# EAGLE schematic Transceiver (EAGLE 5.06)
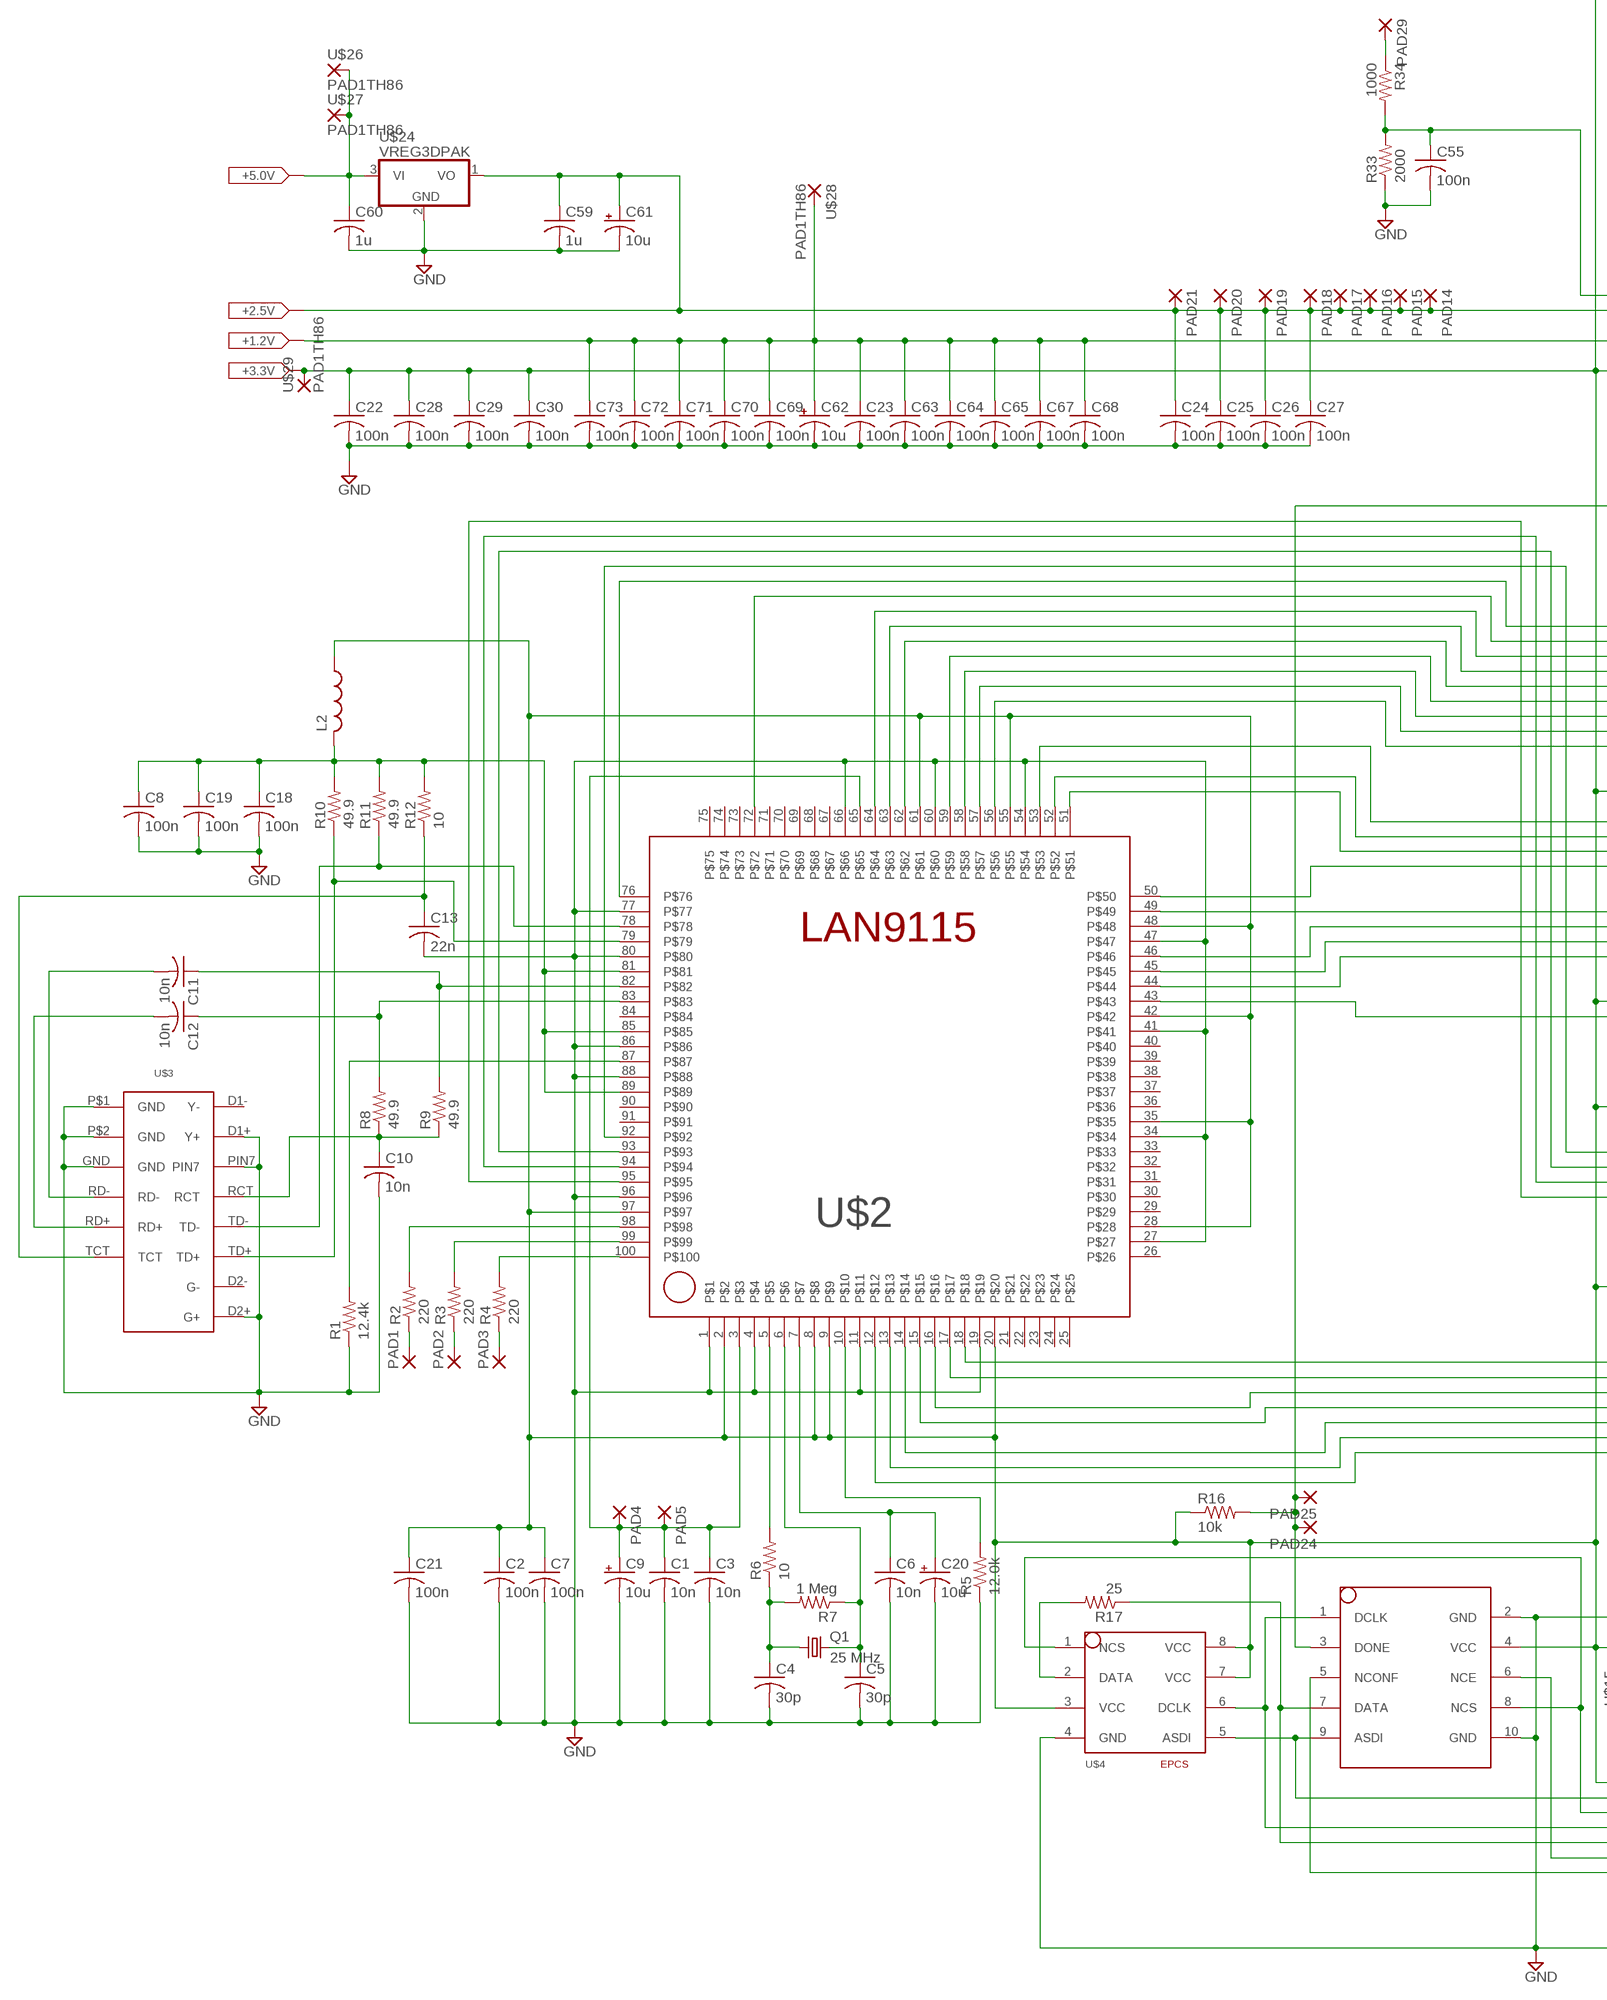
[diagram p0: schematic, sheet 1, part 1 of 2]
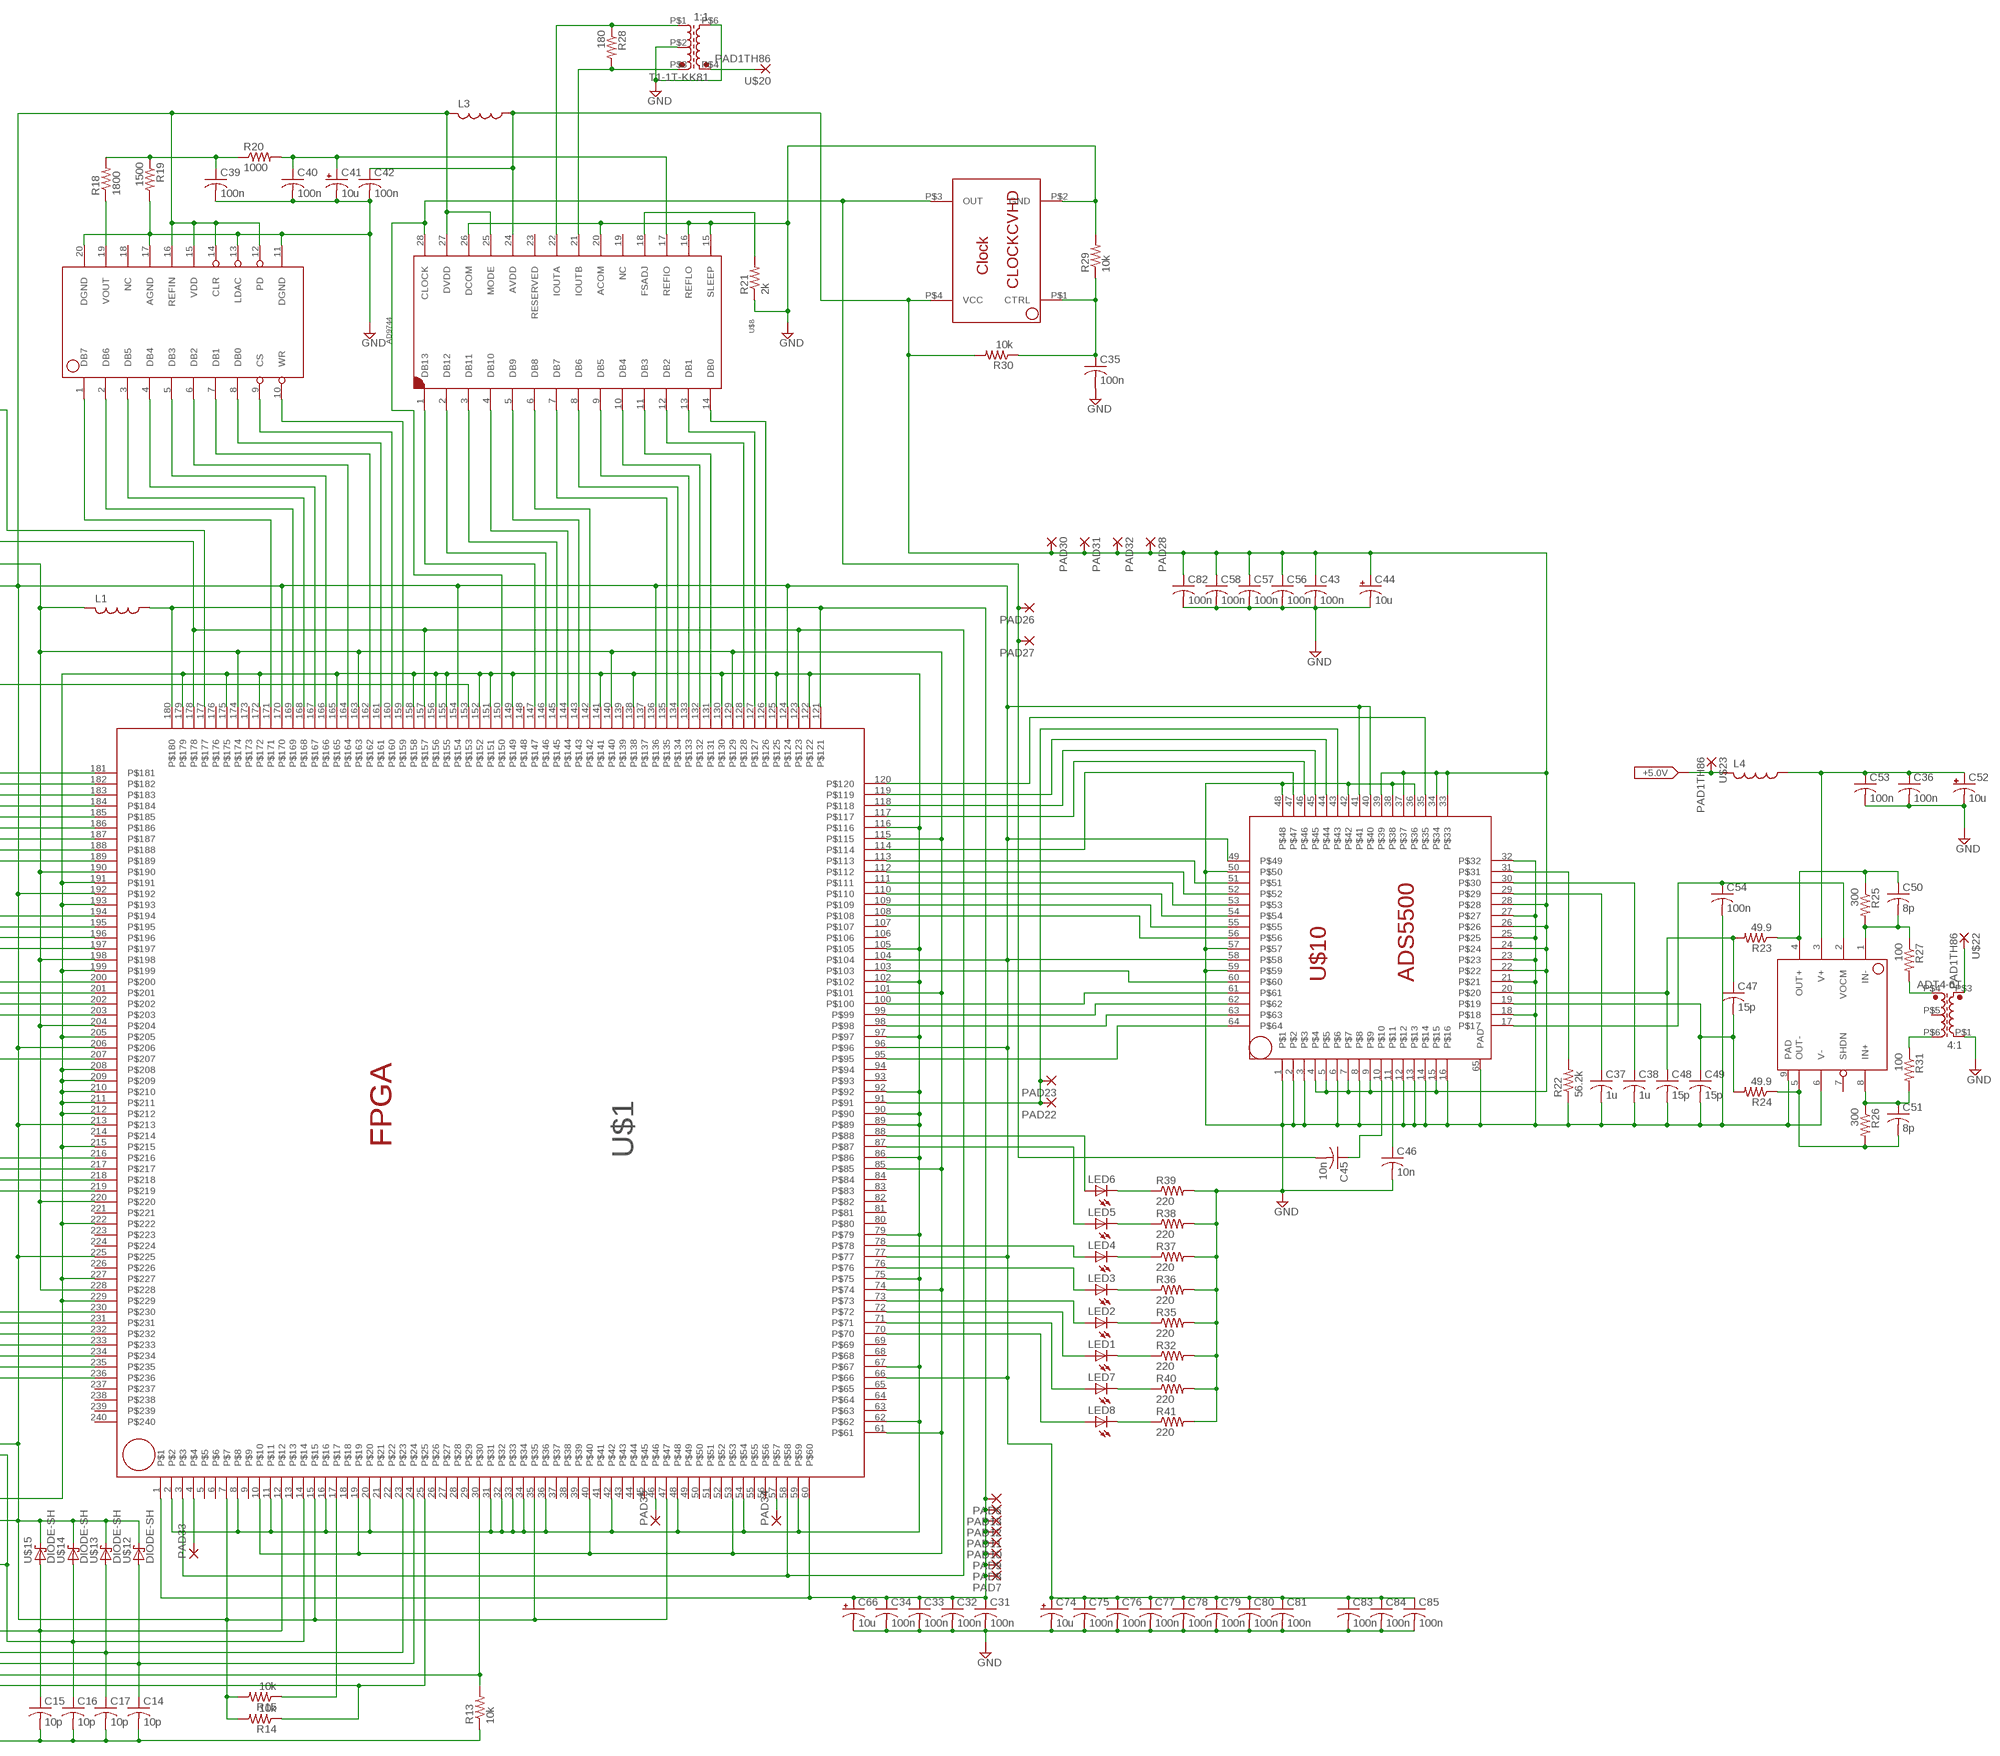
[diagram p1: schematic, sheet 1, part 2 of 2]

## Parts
ADT4-6T  4:1  TRANSF3MINI-CD637  [MINI-CD637]
C1  10n  C-USC0805  [C0805]
C2  100n  C-USC0805  [C0805]
C3  10n  C-USC0805  [C0805]
C4  30p  C-USC0805  [C0805]
C5  30p  C-USC0805  [C0805]
C6  10n  C-USC0805  [C0805]
C7  100n  C-USC0805  [C0805]
C8  100n  C-USC0805  [C0805]
C9  10u  CPOL-USB/3528-21R  [B/3528-21R]
C10  10n  C-USC0805  [C0805]
C11  10n  C-USC0805  [C0805]
C12  10n  C-USC0805  [C0805]
C13  22n  C-USC0805  [C0805]
C14  10p  C-USC0805  [C0805]
C15  10p  C-USC0805  [C0805]
C16  10p  C-USC0805  [C0805]
C17  10p  C-USC0805  [C0805]
C18  100n  C-USC0805  [C0805]
C19  100n  C-USC0805  [C0805]
C20  10u  CPOL-USB/3528-21R  [B/3528-21R]
C21  100n  C-USC0805  [C0805]
C22  100n  C-USC0805  [C0805]
C23  100n  C-USC0805  [C0805]
C24  100n  C-USC0805  [C0805]
C25  100n  C-USC0805  [C0805]
C26  100n  C-USC0805  [C0805]
C27  100n  C-USC0805  [C0805]
C28  100n  C-USC0805  [C0805]
C29  100n  C-USC0805  [C0805]
C30  100n  C-USC0805  [C0805]
C31  100n  C-USC0805  [C0805]
C32  100n  C-USC0805  [C0805]
C33  100n  C-USC0805  [C0805]
C34  100n  C-USC0805  [C0805]
C35  100n  C-USC0805  [C0805]
C36  100n  C-USC0805  [C0805]
C37  1u  C-USC0805  [C0805]
C38  1u  C-USC0805  [C0805]
C39  100n  C-USC0805  [C0805]
C40  100n  C-USC0805  [C0805]
C41  10u  CPOL-USB/3528-21R  [B/3528-21R]
C42  100n  C-USC0805  [C0805]
C43  100n  C-USC0805  [C0805]
C44  10u  CPOL-USB/3528-21R  [B/3528-21R]
C45  10n  C-USC0805  [C0805]
C46  10n  C-USC0805  [C0805]
C47  15p  C-USC0805  [C0805]
C48  15p  C-USC0805  [C0805]
C49  15p  C-USC0805  [C0805]
C50  8p  C-USC0805  [C0805]
C51  8p  C-USC0805  [C0805]
C52  10u  CPOL-USB/3528-21R  [B/3528-21R]
C53  100n  C-USC0805  [C0805]
C54  100n  C-USC0805  [C0805]
C55  100n  C-USC0805  [C0805]
C56  100n  C-USC0805  [C0805]
C57  100n  C-USC0805  [C0805]
C58  100n  C-USC0805  [C0805]
C59  1u  C-USC0805  [C0805]
C60  1u  C-USC0805  [C0805]
C61  10u  CPOL-USB/3528-21R  [B/3528-21R]
C62  10u  CPOL-USB/3528-21R  [B/3528-21R]
C63  100n  C-USC0805  [C0805]
C64  100n  C-USC0805  [C0805]
C65  100n  C-USC0805  [C0805]
C66  10u  CPOL-USB/3528-21R  [B/3528-21R]
C67  100n  C-USC0805  [C0805]
C68  100n  C-USC0805  [C0805]
C69  100n  C-USC0805  [C0805]
C70  100n  C-USC0805  [C0805]
C71  100n  C-USC0805  [C0805]
C72  100n  C-USC0805  [C0805]
C73  100n  C-USC0805  [C0805]
C74  10u  CPOL-USB/3528-21R  [B/3528-21R]
C75  100n  C-USC0805  [C0805]
C76  100n  C-USC0805  [C0805]
C77  100n  C-USC0805  [C0805]
C78  100n  C-USC0805  [C0805]
C79  100n  C-USC0805  [C0805]
C80  100n  C-USC0805  [C0805]
C81  100n  C-USC0805  [C0805]
C82  100n  C-USC0805  [C0805]
C83  100n  C-USC0805  [C0805]
C84  100n  C-USC0805  [C0805]
C85  100n  C-USC0805  [C0805]
L1  L-USL4516C  [L4516C]
L2  L-USL4516C  [L4516C]
L3  L-USL4516C  [L4516C]
L4  L-USL4516C  [L4516C]
LED1  LEDC0805  [C0805]
LED2  LEDC0805  [C0805]
LED3  LEDC0805  [C0805]
LED4  LEDC0805  [C0805]
LED5  LEDC0805  [C0805]
LED6  LEDC0805  [C0805]
LED7  LEDC0805  [C0805]
LED8  LEDC0805  [C0805]
PAD1  2,15/1,0  [2,15/1,0]
PAD2  2,15/1,0  [2,15/1,0]
PAD3  2,15/1,0  [2,15/1,0]
PAD4  1,6/0,8  [1,6/0,8]
PAD5  1,6/0,8  [1,6/0,8]
PAD6  1,6/0,8  [1,6/0,8]
PAD7  1,6/0,8  [1,6/0,8]
PAD8  1,6/0,8  [1,6/0,8]
PAD9  1,6/0,8  [1,6/0,8]
PAD10  1,6/0,8  [1,6/0,8]
PAD11  1,6/0,8  [1,6/0,8]
PAD12  1,6/0,8  [1,6/0,8]
PAD13  1,6/0,8  [1,6/0,8]
PAD14  1,6/0,8  [1,6/0,8]
PAD15  1,6/0,8  [1,6/0,8]
PAD16  1,6/0,8  [1,6/0,8]
PAD17  1,6/0,8  [1,6/0,8]
PAD18  1,6/0,8  [1,6/0,8]
PAD19  1,6/0,8  [1,6/0,8]
PAD20  1,6/0,8  [1,6/0,8]
PAD21  1,6/0,8  [1,6/0,8]
PAD22  1,6/0,8  [1,6/0,8]
PAD23  1,6/0,8  [1,6/0,8]
PAD24  1,6/0,8  [1,6/0,8]
PAD25  1,6/0,8  [1,6/0,8]
PAD26  1,6/0,8  [1,6/0,8]
PAD27  1,6/0,8  [1,6/0,8]
PAD28  1,6/0,8  [1,6/0,8]
PAD29  1,6/0,8  [1,6/0,8]
PAD30  1,6/0,8  [1,6/0,8]
PAD31  1,6/0,8  [1,6/0,8]
PAD32  1,6/0,8  [1,6/0,8]
PAD33  1,6/0,8  [1,6/0,8]
PAD34  1,6/0,8  [1,6/0,8]
PAD35  1,6/0,8  [1,6/0,8]
Q1  25 MHz  CRYSTALTC26V  [TC26V]
R1  12.4k  R-US_R1206  [R1206]
R2  220  R-US_R1206  [R1206]
R3  220  R-US_R1206  [R1206]
R4  220  R-US_R1206  [R1206]
R5  12.0k  R-US_R1206  [R1206]
R6  10  R-US_R1206  [R1206]
R7  1 Meg  R-US_R1206  [R1206]
R8  49.9  R-US_R1206  [R1206]
R9  49.9  R-US_R1206  [R1206]
R10  49.9  R-US_R1206  [R1206]
R11  49.9  R-US_R1206  [R1206]
R12  10  R-US_R1206  [R1206]
R13  10k  R-US_R1206  [R1206]
R14  10k  R-US_R1206  [R1206]
R15  10k  R-US_R1206  [R1206]
R16  10k  R-US_R1206  [R1206]
R17  25  R-US_R1206  [R1206]
R18  1800  R-US_R1206  [R1206]
R19  1500  R-US_R1206  [R1206]
R20  1000  R-US_R1206  [R1206]
R21  2k  R-US_R1206  [R1206]
R22  56.2k  R-US_R0805  [R0805]
R23  49.9  R-US_R0805  [R0805]
R24  49.9  R-US_R0805  [R0805]
R25  300  R-US_R0805  [R0805]
R26  300  R-US_R0805  [R0805]
R27  100  R-US_R0805  [R0805]
R28  180  R-US_R1206  [R1206]
R29  10k  R-US_R1206  [R1206]
R30  10k  R-US_R1206  [R1206]
R31  100  R-US_R0805  [R0805]
R32  220  R-US_R0805  [R0805]
R33  2000  R-US_R1206  [R1206]
R34  1000  R-US_R1206  [R1206]
R35  220  R-US_R0805  [R0805]
R36  220  R-US_R0805  [R0805]
R37  220  R-US_R0805  [R0805]
R38  220  R-US_R0805  [R0805]
R39  220  R-US_R0805  [R0805]
R40  220  R-US_R0805  [R0805]
R41  220  R-US_R0805  [R0805]
T1-1T-KK81  1:1  TRANSF3MINI-KK81  [MINI-KK81]
U$1  EP3C25  [PQFP240]
U$2  LAN9115  [TQFP100]
U$3  MAGJACK2  [MAGJACK2]
U$4  EPCS4  [SOIC-8]
U$5  FPGA-ISP  [2X05]
U$7  CLOCKCVHD  [CLOCKSMD2]
U$8  AD9744  [TSSOP28]
U$9  AD7801  [TSSOP20]
U$10  ADS5500  [LQFP64-PPAD]
U$11  LTC6405  [MSOP8-PPAD]
U$12  DIODE-SH  [SOD323R_INFINEON]
U$13  DIODE-SH  [SOD323R_INFINEON]
U$14  DIODE-SH  [SOD323R_INFINEON]
U$15  DIODE-SH  [SOD323R_INFINEON]
U$20  PAD1TH86  [PAD100]
U$22  PAD1TH86  [PAD100]
U$23  PAD1TH86  [PAD100]
U$24  VREG3DPAK  VREG3DPAK-OGI  [DPAK]
U$26  PAD1TH86  [PAD100]
U$27  PAD1TH86  [PAD100]
U$28  PAD1TH86  [PAD100]
U$29  PAD1TH86  [PAD100]

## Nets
+1.2V: C23.1 C62.+ C63.1 C64.1 C65.1 C67.1 C68.1 C69.1 C70.1 C71.1 C72.1 C73.1 L1.2 U$1.10 U$1.19 U$1.40 U$1.53 U$1.61 U$1.74 U$1.85 U$1.101 U$1.115 U$1.129 U$1.140 U$1.163 U$1.174 U$1.190 U$1.198 U$1.204 U$1.220 U$1.228 U$28.1(P) ; supply symbol labelled V+1.2
+2.5V: C24.1 C25.1 C26.1 C27.1 C59.1 C61.+ PAD14.1(P) PAD15.1(P) PAD16.1(P) PAD17.1(P) PAD18.1(P) PAD19.1(P) PAD20.1(P) PAD21.1(P) U$1.3 U$1.58 U$1.123 U$1.157 U$1.178 U$24.1(VO) ; supply symbol labelled V+2.5
+3.3V: C2.1 C7.1 C21.1 C22.1 C28.1 C29.1 C30.1 C74.+ C75.1 C76.1 C77.1 C78.1 C79.1 C80.1 C81.1 C83.1 C84.1 C85.1 L2.1 L3.2 R14.2 R15.2 R16.1 U$1.7 U$1.15 U$1.35 U$1.47 U$1.66 U$1.77 U$1.96 U$1.104 U$1.124 U$1.136 U$1.154 U$1.170 U$1.192 U$1.206 U$1.213 U$1.225 U$2.2 U$2.8 U$2.9 U$2.20 U$2.28 U$2.35 U$2.42 U$2.48 U$2.55 U$2.61 U$2.97 U$4.3(VCC) U$4.7(VCC) U$4.8(VCC) U$5.4(VCC) U$8.25(MODE) U$8.27(DVDD) U$9.12(PD) U$9.14(CLR) U$9.15(VDD) U$9.16(REFIN) U$10.40 U$10.41 U$10.49 U$10.58 U$12.C U$13.C U$14.C U$15.C U$29.1(P) ; supply symbol labelled V+3.3
+5.0V: C60.1 L4.2 U$23.1(P) U$24.3(VI) U$26.1(P) U$27.1(P) ; supply symbol labelled V+5.0
AVCC: C42.1 C43.1 C44.+ C56.1 C57.1 C58.1 C82.1 L3.1 PAD28.1(P) PAD30.1(P) PAD31.1(P) PAD32.1(P) R30.2 U$7.P$4(VCC) U$8.24(AVDD) U$10.4 U$10.5 U$10.7 U$10.9 U$10.15 U$10.22 U$10.24 U$10.26 U$10.28 U$10.33 U$10.34 U$10.37 U$10.39
GND: ADT4-6T.P$1 C1.2 C2.2 C3.2 C4.2 C5.2 C6.2 C7.2 C8.2 C9.- C10.2 C13.2 C14.2 C15.2 C16.2 C17.2 C18.2 C19.2 C20.- C21.2 C22.2 C23.2 C24.2 C25.2 C26.2 C27.2 C28.2 C29.2 C30.2 C31.2 C32.2 C33.2 C34.2 C35.2 C36.2 C37.2 C38.2 C39.2 C40.2 C41.- C42.2 C43.2 C44.- C46.2 C48.2 C49.2 C52.- C53.2 C54.2 C55.2 C56.2 C57.2 C58.2 C59.2 C60.2 C61.- C62.- C63.2 C64.2 C65.2 C66.- C67.2 C68.2 C69.2 C70.2 C71.2 C72.2 C73.2 C74.- C75.2 C76.2 C77.2 C78.2 C79.2 C80.2 C81.2 C82.2 C83.2 C84.2 C85.2 R1.1 R5.1 R13.1 R19.2 R21.1 R22.1 R29.2 R32.2 R33.1 R35.2 R36.2 R37.2 R38.2 R39.2 R40.2 R41.2 T1-1T-KK81.P$2 T1-1T-KK81.P$6 U$1.2 U$1.8 U$1.11 U$1.16 U$1.20 U$1.31 U$1.32 U$1.33 U$1.34 U$1.36 U$1.42 U$1.48 U$1.54 U$1.59 U$1.62 U$1.67 U$1.75 U$1.79 U$1.86 U$1.89 U$1.90 U$1.92 U$1.97 U$1.102 U$1.105 U$1.116 U$1.122 U$1.125 U$1.130 U$1.138 U$1.141 U$1.149 U$1.151 U$1.152 U$1.155 U$1.156 U$1.158 U$1.165 U$1.172 U$1.175 U$1.179 U$1.191 U$1.193 U$1.199 U$1.205 U$1.208 U$1.209 U$1.210 U$1.211 U$1.212 U$1.215 U$1.222 U$1.227 U$1.229 U$2.1 U$2.4 U$2.11 U$2.19 U$2.27 U$2.34 U$2.41 U$2.47 U$2.54 U$2.60 U$2.66 U$2.77 U$2.80 U$2.86 U$2.88 U$2.96 U$3.D1+(Y+) U$3.D2+(G+) U$3.GND U$3.P$1(GND) U$3.P$2(GND) U$3.PIN7 U$4.4(GND) U$5.2(GND) U$5.10(GND) U$7.P$2(GND) U$8.15(SLEEP) U$8.16(REFLO) U$8.20(ACOM) U$8.26(DCOM) U$9.11(DGND) U$9.13(LDAC) U$9.17(AGND) U$9.20(DGND) U$10.1 U$10.2 U$10.3 U$10.6 U$10.8 U$10.12 U$10.13 U$10.14 U$10.16 U$10.18 U$10.21 U$10.23 U$10.25 U$10.27 U$10.32 U$10.36 U$10.38 U$10.42 U$10.48 U$10.50 U$10.57 U$10.59 U$10.65(PAD) U$11.6(V-) U$11.9(PAD) U$24.2(GND)
N$1: C8.1 C18.1 C19.1 L2.2 R10.2 R11.2 R12.2 U$2.81 U$2.85 U$2.89
N$2: C1.1 C3.1 C9.+ PAD4.1(P) PAD5.1(P) U$2.3 U$2.65
N$3: C4.1 Q1.1 R6.1 R7.2
N$4: U$1.183 U$2.64
N$5: R6.2 U$2.5
N$6: C5.1 Q1.2 R7.1 U$2.6
N$7: C6.1 C20.+ U$2.7
N$8: R5.2 U$2.10
N$9: R4.2 U$2.100
N$10: R3.2 U$2.99
N$11: R2.2 U$2.98
N$12: R1.2 U$2.87
N$13: U$1.230 U$2.18
N$14: U$1.231 U$2.17
N$15: U$1.232 U$2.16
N$16: U$1.233 U$2.15
N$17: U$1.234 U$2.14
N$18: U$1.235 U$2.13
N$19: U$1.236 U$2.12
N$20: U$1.207 U$2.43
N$21: U$1.203 U$2.44
N$22: U$1.202 U$2.45
N$23: U$1.201 U$2.46
N$24: U$1.200 U$2.49
N$25: U$1.197 U$2.50
N$26: U$1.196 U$2.51
N$27: U$1.195 U$2.52
N$28: U$1.194 U$2.53
N$29: U$1.189 U$2.56
N$30: U$1.188 U$2.57
N$31: U$1.187 U$2.58
N$32: U$1.186 U$2.59
N$33: U$1.185 U$2.62
N$34: U$1.184 U$2.63
N$35: R18.1 U$9.19(VOUT)
N$36: U$1.182 U$2.72
N$37: U$1.181 U$2.76
N$38: U$1.216 U$2.92
N$39: U$1.217 U$2.93
N$40: U$1.218 U$2.94
N$41: U$1.219 U$2.95
N$42: C10.1 R8.1 R9.1 U$3.RCT
N$43: C12.1 R8.2 U$2.83
N$44: C11.1 R9.2 U$2.82
N$45: C13.1 R12.1 U$3.TCT
N$46: R11.1 U$2.78 U$3.TD-
N$47: R10.1 U$2.79 U$3.TD+
N$48: U$1.113 U$10.51
N$49: C45.2 PAD26.1(P) PAD27.1(P) U$1.150 U$7.P$3(OUT) U$8.28(CLOCK)
N$50: R14.1 U$1.25 U$5.5(NCONF)
N$51: C17.1 U$1.23 U$4.6(DCLK) U$5.1(DCLK) U$13.A
N$52: C14.1 R17.1 U$1.24 U$5.7(DATA) U$12.A
N$53: C16.1 U$1.14 U$4.1(NCS) U$5.8(NCS) U$14.A
N$54: C15.1 U$1.12 U$4.5(ASDI) U$5.9(ASDI) U$15.A
N$55: U$1.126 U$8.14(DB0)
N$56: PAD24.1(P) PAD25.1(P) R16.2 U$1.153 U$5.3(DONE)
N$57: R15.1 U$1.17
N$58: PAD1.1(P) R2.1
N$59: PAD2.1(P) R3.1
N$60: PAD3.1(P) R4.1
N$61: R13.2 U$1.30 U$5.6(NCE)
N$62: U$1.127 U$8.13(DB1)
N$63: U$1.128 U$8.12(DB2)
N$64: C11.2 U$3.RD-
N$65: C12.2 U$3.RD+
N$66: U$1.131 U$8.11(DB3)
N$67: U$1.132 U$8.10(DB4)
N$68: U$1.133 U$8.9(DB5)
N$69: U$1.134 U$8.8(DB6)
N$70: U$1.135 U$8.7(DB7)
N$71: U$1.142 U$8.6(DB8)
N$72: U$1.143 U$8.5(DB9)
N$73: U$1.144 U$8.4(DB10)
N$74: U$1.145 U$8.3(DB11)
N$75: U$1.146 U$8.2(DB12)
N$76: U$1.147 U$8.1(DB13)
N$77: U$1.171 U$9.1(DB7)
N$78: U$1.169 U$9.2(DB6)
N$79: U$1.168 U$9.3(DB5)
N$80: U$1.167 U$9.4(DB4)
N$81: U$1.159 U$9.10(WR)
N$82: U$1.160 U$9.9(CS)
N$83: U$1.161 U$9.8(DB0)
N$84: U$1.162 U$9.7(DB1)
N$85: U$1.164 U$9.6(DB2)
N$86: U$1.166 U$9.5(DB3)
N$87: R17.2 U$4.2(DATA)
N$88: C39.1 R18.2 R19.1 R20.1
N$89: C40.1 C41.+ R20.2 U$8.17(REFIO)
N$90: R28.2 T1-1T-KK81.P$3 U$8.21(IOUTB)
N$91: R21.2 U$8.18(FSADJ)
N$93: U$1.120 U$10.35
N$94: PAD22.1(P) PAD23.1(P) U$1.91 U$10.43
N$95: U$1.119 U$10.44
N$96: U$1.118 U$10.45
N$97: C55.1 R33.2 R34.2 U$1.177
N$98: PAD33.1(P) U$1.4
N$99: PAD34.1(P) U$1.57
N$100: PAD35.1(P) U$1.46
N$101: PAD29.1(P) R34.1
N$102: U$1.117 U$10.46
N$103: LED6.1(A) U$1.88
N$104: LED6.2(C) R39.1
N$105: LED5.1(A) U$1.87
N$106: LED5.2(C) R38.1
N$107: LED4.1(A) U$1.78
N$108: U$1.114 U$10.47
N$109: U$1.112 U$10.52
N$110: U$1.111 U$10.53
N$111: U$1.110 U$10.54
N$112: U$1.109 U$10.55
N$113: U$1.108 U$10.56
N$114: U$1.103 U$10.60
N$115: U$1.100 U$10.61
N$116: R22.2 U$10.31
N$117: R28.1 T1-1T-KK81.P$1 U$8.22(IOUTA)
N$118: U$1.99 U$10.62
N$119: ADT4-6T.P$3 U$22.1(P)
N$120: C36.1 C52.+ C53.1 L4.1 U$11.3(V+)
N$121: C35.1 R29.1 R30.1 U$7.P$1(CTRL)
N$122: T1-1T-KK81.P$4 U$20.1(P)
N$123: C54.1 U$10.17 U$11.2(VOCM)
N$124: LED4.2(C) R37.1
N$125: LED3.2(C) R36.1
N$126: U$1.98 U$10.63
N$127: U$1.95 U$10.64
N$128: LED3.1(A) U$1.76
N$129: C38.1 U$10.30
N$130: LED2.1(A) U$1.73
N$131: C37.1 U$10.29
N$132: C46.1 U$10.11
N$133: C45.1 U$10.10
N$134: C47.2 C49.1 R24.2 U$10.19
N$135: C50.2 R25.2 R27.1 U$11.1(IN-)
N$136: C50.1 R23.1 R25.1 U$11.4(OUT+)
N$137: C47.1 C48.1 R23.2 U$10.20
N$138: C51.1 R26.1 R31.2 U$11.8(IN+)
N$139: C51.2 R24.1 R26.2 U$11.5(OUT-)
N$140: ADT4-6T.P$6 R31.1
N$141: ADT4-6T.P$4 R27.2
N$142: LED2.2(C) R35.1
N$143: LED1.1(A) U$1.72
N$144: LED1.2(C) R32.1
N$145: LED7.1(A) U$1.71
N$146: LED7.2(C) R40.1
N$147: LED8.1(A) U$1.70
N$148: LED8.2(C) R41.1
VCCD_PLL: C31.1 C32.1 C33.1 C34.1 C66.+ L1.1 PAD6.1(P) PAD7.1(P) PAD8.1(P) PAD9.1(P) PAD10.1(P) PAD11.1(P) PAD12.1(P) PAD13.1(P) U$1.1 U$1.60 U$1.121 U$1.180
Unconnected: ADT4-6T.P$5 U$1.5 U$1.6 U$1.9 U$1.13 U$1.18 U$1.21 U$1.22 U$1.26 U$1.27 U$1.28 U$1.29 U$1.37 U$1.38 U$1.39 U$1.41 U$1.43 U$1.44 U$1.45 U$1.49 U$1.50 U$1.51 U$1.52 U$1.55 U$1.56 U$1.63 U$1.64 U$1.65 U$1.68 U$1.69 U$1.80 U$1.81 U$1.82 U$1.83 U$1.84 U$1.93 U$1.94 U$1.106 U$1.107 U$1.137 U$1.139 U$1.148 U$1.173 U$1.176 U$1.214 U$1.221 U$1.223 U$1.224 U$1.226 U$1.237 U$1.238 U$1.239 U$1.240 U$2.21 U$2.22 U$2.23 U$2.24 U$2.25 U$2.26 U$2.29 U$2.30 U$2.31 U$2.32 U$2.33 U$2.36 U$2.37 U$2.38 U$2.39 U$2.40 U$2.67 U$2.68 U$2.69 U$2.70 U$2.71 U$2.73 U$2.74 U$2.75 U$2.84 U$2.90 U$2.91 U$3.D1-(Y-) U$3.D2-(G-) U$8.19(NC) U$8.23(RESERVED) U$9.18(NC) U$11.7(SHDN)

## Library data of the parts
ADT4-6T T1-1T-KK81 = Jim:TRANSF3
C1-C8 C10-C19 C21-C40 C42 C43 C45-C51 C53-C60 C63-C65 C67-C73 C75-C85 = rcl:C-US: CAPACITOR, American symbol
C9 C20 C41 C44 C52 C61 C62 C66 C74 = rcl:CPOL-US: POLARIZED CAPACITOR, American symbol
L1-L4 = rcl:L-US: INDUCTOR, American symbol
LED1-LED8 = Jim:LED
PAD1-PAD3 = wirepad:2,15/1,0: THROUGH-HOLE PAD
PAD4-PAD35 = wirepad:1,6/0,8: THROUGH-HOLE PAD
Q1 = crystal:CRYSTAL: CRYSTAL
R1-R41 = rcl:R-US_: RESISTOR, American symbol
U$1 = Jim:EP3C25
U$2 = Jim:LAN9115
U$3 = Jim:MAGJACK2
U$4 = Jim:EPCS4
U$5 = Jim:FPGA-ISP
U$7 = Jim:CLOCKCVHD
U$8 = Jim:AD9744
U$9 = Jim:AD7801
U$10 = Jim:ADS5500
U$11 = Jim:LTC6405
U$12-U$15 = Jim:DIODE-SH
U$20 U$22 U$23 U$26-U$29 = Jim:PAD1
U$24 = Jim:VREG3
